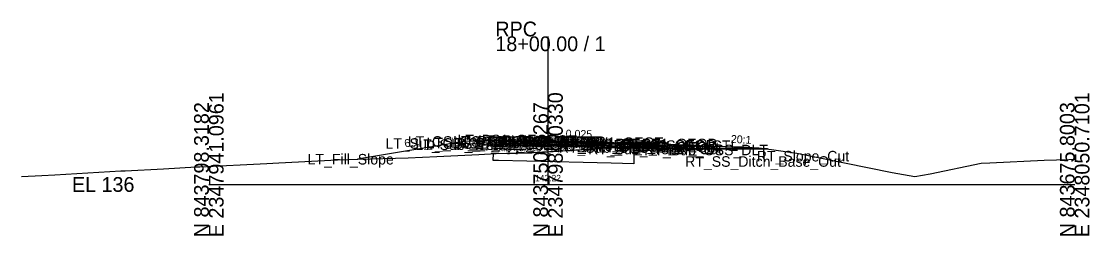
# Model space of a CAD drawing. Extents: x -26 to 203, y -10 to 7538.
# Drawn here: x 0 to 202.8, y 4490.3 to 4530.9 of the extents above; entities that cross this region are included whole.
import ezdxf

# ---------------------------------------------------------------- set-up
doc = ezdxf.new("R2010")
doc.units = 0
for name, color, linetype in [('Default', 7, 'Continuous'), ('Exist Cross Section Cell', 7, 'Continuous'), ('Exist XS Center Line Elevation Label', 7, 'Continuous'), ('Exist XS Ground Line', 7, 'Continuous'), ('Prop CMT Pvmt Course 1', 7, 'Continuous'), ('Prop CMT Pvmt Course 2', 7, 'Continuous'), ('Prop CMT Pvmt Course 3', 7, 'Continuous'), ('Prop CMT Pvmt Surface', 7, 'Continuous'), ('Prop CMT Pvmt Surface Shoulder', 7, 'Continuous'), ('Prop CMT Shld Paved Course 1', 7, 'Continuous'), ('Prop CMT Shld Paved Course 2', 7, 'Continuous'), ('Prop CMT Shld Paved Course 3', 7, 'Continuous'), ('Prop CMT Slope Grass', 7, 'Continuous'), ('Prop CMT Subgrade Earthwork', 7, 'Continuous'), ('Prop Road Sect_ Recs - UC (Outline)', 7, 'Continuous'), ('Prop XS Earthwork Shape', 7, 'Continuous'), ('Prop XS SE Text', 7, 'Continuous'), ('Prop XS Side Slope Text', 7, 'Continuous'), ('Scratch_Level_0', 7, 'Continuous')]:
    doc.layers.add(name, color=color, linetype=linetype)

msp = doc.modelspace()

# ---------------------------------------------------------------- linework, layer by layer
at = {"layer": 'Exist Cross Section Cell'}
for p, q in [((100, 4500), (100, 4528.08)), ((35.6, 4500), (100, 4500)), ((100, 4500), (200, 4500))]:
    msp.add_line(p, q, dxfattribs=at)
at = {"layer": 'Exist XS Ground Line'}
msp.add_lwpolyline([(0, 4501.51), (3.9, 4501.7), (6.33, 4501.84), (18.89, 4502.56), (19.74, 4502.6), (26.97, 4502.99), (33.16, 4503.32), (33.51, 4503.34), (33.89, 4503.35), (46.58, 4503.96), (48.89, 4504.08), (60, 4504.67), (63.89, 4504.79), (73.42, 4505.03), (78.89, 4505.31), (86.84, 4505.71), (90.16, 4505.85), (93.88, 4505.94), (97.25, 4506.09), (100.25, 4506.23), (109.27, 4506.8), (116.3, 4507.22), (116.62, 4507.23), (117.72, 4507.31), (118.44, 4507.35), (119.33, 4507.36), (119.79, 4507.37), (120.77, 4507.37), (123.01, 4507.35), (123.72, 4507.35), (124.53, 4507.34), (125.5, 4507.34), (126.35, 4507.33), (127.25, 4507.31), (128.27, 4507.29), (129.72, 4507.27), (132.01, 4507.22), (133.04, 4507.2), (135.73, 4507.14), (136.33, 4507.13), (136.82, 4507.11), (137.83, 4507.08), (138.76, 4507.03), (139.56, 4506.96), (140.04, 4506.97), (142.41, 4506.66), (147.24, 4505.93), (165.35, 4502.29), (169.64, 4501.49), (172.59, 4502.01), (182.23, 4504.07), (183.87, 4504.13), (194.18, 4504.63), (198.87, 4504.76), (200, 4504.78)], dxfattribs=at)
at = {"layer": 'Prop CMT Pvmt Course 1'}
for p, q in [((100, 4508.23), (96, 4508.33)), ((96, 4508.33), (96, 4508.08)), ((96, 4508.08), (100, 4507.98)), ((100, 4507.98), (100, 4508.23)), ((100, 4508.23), (112, 4507.93)), ((100, 4507.98), (100, 4508.23)), ((100, 4507.98), (100, 4508.1)), ((100, 4508.1), (100, 4508.1)), ((100, 4508.1), (100, 4507.98)), ((100, 4507.98), (100, 4508.1)), ((100, 4508.1), (100, 4508.1)), ((100, 4508.1), (100, 4507.98)), ((100, 4507.98), (100, 4507.98)), ((112, 4507.68), (100, 4507.98)), ((100, 4507.98), (100, 4507.98)), ((112, 4507.93), (112, 4507.68))]:
    msp.add_line(p, q, dxfattribs=at)
at = {"layer": 'Prop CMT Pvmt Course 2'}
for p, q in [((100, 4507.98), (96, 4508.08)), ((96, 4508.08), (96, 4507.75)), ((96, 4507.75), (100, 4507.65)), ((100, 4507.65), (100, 4507.98)), ((100, 4507.65), (100, 4507.98)), ((100, 4507.98), (112, 4507.68)), ((112, 4507.35), (100, 4507.65)), ((112, 4507.68), (112, 4507.35))]:
    msp.add_line(p, q, dxfattribs=at)
at = {"layer": 'Prop CMT Pvmt Course 3'}
for p, q in [((100, 4507.65), (96, 4507.75)), ((96, 4507.75), (96, 4507.41)), ((96, 4507.41), (100, 4507.31)), ((100, 4507.31), (100, 4507.65)), ((100, 4507.65), (112, 4507.35)), ((100, 4507.31), (100, 4507.65)), ((112, 4507.01), (100, 4507.31)), ((112, 4507.35), (112, 4507.01))]:
    msp.add_line(p, q, dxfattribs=at)
at = {"layer": 'Prop CMT Pvmt Surface'}
for q in [(96, 4508.33), (112, 4507.93)]:
    msp.add_line((100, 4508.23), q, dxfattribs=at)
at = {"layer": 'Prop CMT Pvmt Surface Shoulder'}
for p, q in [((96, 4508.33), (92, 4508.43)), ((112, 4507.93), (122, 4507.68))]:
    msp.add_line(p, q, dxfattribs=at)
at = {"layer": 'Prop CMT Shld Paved Course 1'}
for p, q in [((92, 4508.43), (91.76, 4508.19)), ((91.76, 4508.19), (96, 4508.08)), ((96, 4508.33), (92, 4508.43)), ((96, 4508.08), (96, 4508.33)), ((112, 4507.93), (122, 4507.68)), ((112, 4507.68), (112, 4507.93)), ((122.26, 4507.42), (112, 4507.68)), ((122, 4507.68), (122.26, 4507.42))]:
    msp.add_line(p, q, dxfattribs=at)
at = {"layer": 'Prop CMT Shld Paved Course 2'}
for p, q in [((91.76, 4508.19), (91.43, 4507.86)), ((91.43, 4507.86), (96, 4507.75)), ((96, 4508.08), (91.76, 4508.19)), ((96, 4507.75), (96, 4508.08)), ((112, 4507.68), (122.26, 4507.42)), ((112, 4507.35), (112, 4507.68)), ((122.6, 4507.08), (112, 4507.35)), ((122.26, 4507.42), (122.6, 4507.08))]:
    msp.add_line(p, q, dxfattribs=at)
at = {"layer": 'Prop CMT Shld Paved Course 3'}
for p, q in [((90.93, 4507.87), (90.61, 4507.55)), ((90.61, 4507.55), (96, 4507.41)), ((91.43, 4507.86), (90.93, 4507.87)), ((96, 4507.75), (91.43, 4507.86)), ((96, 4507.41), (96, 4507.75)), ((112, 4507.35), (122.6, 4507.08)), ((112, 4507.01), (112, 4507.35)), ((123.44, 4506.73), (112, 4507.01)), ((122.6, 4507.08), (123.1, 4507.07)), ((123.1, 4507.07), (123.44, 4506.73))]:
    msp.add_line(p, q, dxfattribs=at)
at = {"layer": 'Prop CMT Slope Grass'}
for p, q in [((84, 4508.15), (63.84, 4504.79)), ((92, 4508.43), (84, 4508.15)), ((122, 4507.68), (126, 4507.54)), ((126, 4507.54), (141.78, 4506.75))]:
    msp.add_line(p, q, dxfattribs=at)
at = {"layer": 'Prop CMT Subgrade Earthwork'}
for p, q in [((90.61, 4507.55), (81.72, 4507.77)), ((96, 4507.41), (90.61, 4507.55)), ((100, 4507.31), (96, 4507.41)), ((100, 4507.31), (112, 4507.01)), ((112, 4507.01), (123.44, 4506.73)), ((123.44, 4506.73), (141.78, 4506.75))]:
    msp.add_line(p, q, dxfattribs=at)
at = {"layer": 'Prop Road Sect_ Recs - UC (Outline)'}
msp.add_lwpolyline([(116.27, 4503.91), (112, 4504.01), (96, 4504.41), (90.61, 4504.55), (89.61, 4504.57), (89.64, 4505.85), (90.16, 4505.85), (100, 4506.22), (109.27, 4506.8), (112, 4507.01), (116.27, 4506.91), (116.28, 4506.91), (116.27, 4503.91)], close=True, dxfattribs=at)
at = {"layer": 'Prop XS Earthwork Shape'}
for points in [[(63.84, 4504.79), (63.89, 4504.79), (73.42, 4505.03), (78.89, 4505.31), (86.84, 4505.71), (90.16, 4505.85), (93.88, 4505.94), (97.25, 4506.09), (100.25, 4506.23), (109.27, 4506.8), (112.61, 4507), (112, 4507.01), (100, 4507.31), (96, 4507.41), (90.61, 4507.55), (81.72, 4507.77)], [(112.61, 4507), (116.3, 4507.22), (116.62, 4507.23), (117.72, 4507.31), (118.44, 4507.35), (119.33, 4507.36), (119.79, 4507.37), (120.77, 4507.37), (123.01, 4507.35), (123.72, 4507.35), (124.53, 4507.34), (125.5, 4507.34), (126.35, 4507.33), (127.25, 4507.31), (128.27, 4507.29), (129.72, 4507.27), (132.01, 4507.22), (132.75, 4507.2), (141.64, 4506.76), (141.7, 4506.75), (123.44, 4506.73)], [(138.76, 4507.03), (139.56, 4506.96), (140.04, 4506.97), (141.64, 4506.76), (132.75, 4507.2), (133.04, 4507.2), (135.73, 4507.14), (136.33, 4507.13), (136.82, 4507.11), (137.83, 4507.08)]]:
    msp.add_lwpolyline(points, close=True, dxfattribs=at)

# ---------------------------------------------------------------- texts
at = {"layer": 'Default'}
msp.add_text('-', height=0.0001, dxfattribs=at).set_placement((35.6, 4500))
at = {"layer": 'Exist Cross Section Cell'}
for s, p in [('RPC', (90, 4528.08)), ('18+00.00 / 1', (90, 4525.28)), ('EL 136', (9.6, 4498.6))]:
    msp.add_text(s, height=2.8, dxfattribs=at).set_placement(p)
for s, p in [('E 2347941.0961', (38.4, 4490)), ('E 2347984.0330', (102.8, 4490)), ('E 2348050.7101', (202.8, 4490)), ('N 843798.3182', (35.6, 4490)), ('N 843750.3267', (100, 4490)), ('N 843675.8003', (200, 4490))]:
    msp.add_text(s, height=2.8, rotation=90, dxfattribs=at).set_placement(p)
at = {"layer": 'Exist XS Center Line Elevation Label'}
msp.add_text('142.22', height=1.2, dxfattribs=at).set_placement((97.55, 4500.62))
at = {"layer": 'Prop XS SE Text'}
msp.add_text('0.025', height=1.5, rotation=358.5679, dxfattribs=at).set_placement((103.34, 4508.9))
at = {"layer": 'Prop XS Side Slope Text'}
for s, rotation, p in [('20:1', 357.1376, (134.69, 4507.89)), ('6:1', 9.4623, (72.85, 4507.03))]:
    msp.add_text(s, height=1.5, rotation=rotation, dxfattribs=at).set_placement(p)
at = {"layer": 'Scratch_Level_0'}
for s, p in [('LT_GS_OS_CTL', (73.37, 4507.15)), ('LT_PS2_OEOP', (81.99, 4507.19)), ('LT_PS1_OEOP', (82.8, 4507.43)), ('LT_PV1_OEOT', (86.74, 4507.33)), ('RT_PV1_OEEOP', (89.83, 4507.1)), ('LT_PV1_OEEOP', (89.87, 4507.1)), ('RT_PV1_IEEOP', (90.47, 4507.1)), ('LT_PV1_IEEOP', (90.52, 4507.1)), ('PV1_PGL', (94.47, 4507.23)), ('LT_Sub_OSS_DLT', (69.12, 4506.77)), ('LT_Sub_Trench_Out', (74.81, 4506.55)), ('LT_PS3_Shelf_Out', (76.92, 4506.87)), ('LT_PS3_OEOP', (81.67, 4506.86)), ('LT_Sub_OEOT', (86.08, 4506.41)), ('LT_PV2_OEOT', (86.17, 4507.08)), ('LT_PV3_OEOT', (86.17, 4506.75)), ('RT_Sub_OEEOP', (89.17, 4506.31)), ('LT_Sub_OEEOP', (89.21, 4506.31)), ('RT_PV2_OEEOP', (89.26, 4506.98)), ('RT_PV3_OEEOP', (89.26, 4506.65)), ('LT_PV2_OEEOP', (89.31, 4506.98)), ('LT_PV3_OEEOP', (89.31, 4506.65)), ('RT_PV2_IEEOP', (89.91, 4506.98)), ('LT_PV2_IEEOP', (89.95, 4506.98)), ('PV2_PGL', (93.91, 4506.98)), ('RT_Sub_OEOT', (102.03, 4506.01)), ('RT_PV2_OEOT', (102.13, 4506.68)), ('RT_PV3_OEOT', (102.13, 4506.35)), ('RT_PV1_OEOT', (102.69, 4506.93)), ('RT_Sub_Trench_Out', (107.6, 4505.73)), ('RT_PS3_Shelf_Out', (109.04, 4506.07)), ('RT_PS2_OEOP', (112.45, 4506.42)), ('RT_PS1_OEOP', (112.76, 4506.68)), ('RT_PS3_OEOP', (112.79, 4506.08)), ('RT_GS_OS_CTL', (115.32, 4506.36)), ('RT_Sub_OSS_DLT', (118.27, 4505.54)), ('LT_Fill_Slope', (54.36, 4503.79)), ('RT_SS_Ditch_Base_Out', (126.03, 4503.36)), ('RT_Slope_Cut', (139.63, 4504.37))]:
    msp.add_text(s, height=2, dxfattribs=at).set_placement(p)

doc.saveas('drawing.dxf')
